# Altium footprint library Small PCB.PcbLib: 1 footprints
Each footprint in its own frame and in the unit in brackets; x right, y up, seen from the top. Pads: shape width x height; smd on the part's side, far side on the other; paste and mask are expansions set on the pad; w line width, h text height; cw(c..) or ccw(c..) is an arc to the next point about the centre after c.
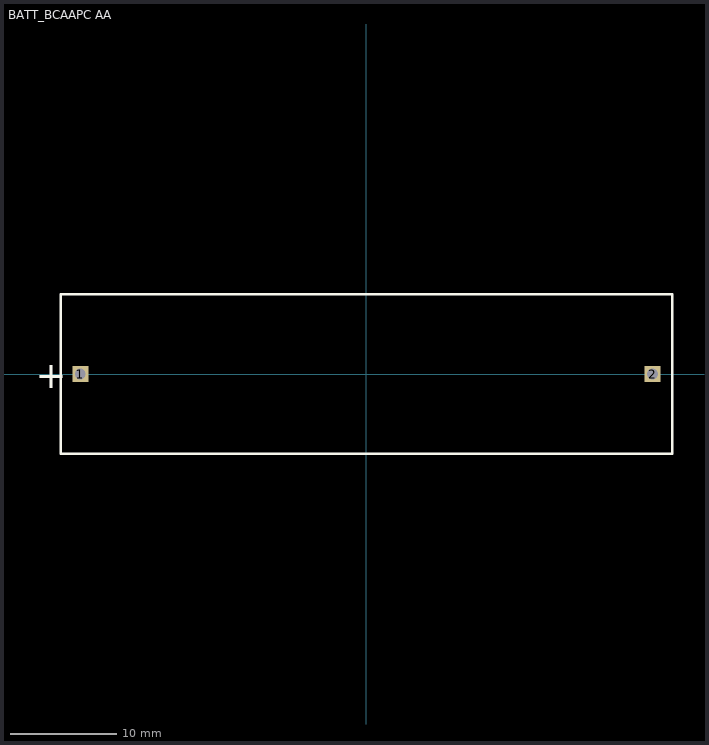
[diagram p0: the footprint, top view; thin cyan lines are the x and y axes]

## BATT_BCAAPC AA [mm]
height 13.9
pads (2):
  rect 1.5x1.5 hole 1 mask+0.102: 1(-26.9,0) 2(26.9,0)
Top Overlay:
  lines w0.203: -28.75,-7.5 28.75,-7.5 28.75,7.5 -28.75,7.5 -28.75,-7.5
  text "+" at -31.09,-1.321 h2.54
Mechanical 1:
  text "'.Designator'" at 0,0 h1.52
Mechanical 15:
  lines w0.127: -28.75,-7.5 -28.75,7.5 28.75,7.5 28.75,-7.5 -28.75,-7.5
  text "+" at -27.906,-1.279 h2.54
3D body: height 13.9, standoff 0, extent -28.75,-7.5 28.75,7.5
